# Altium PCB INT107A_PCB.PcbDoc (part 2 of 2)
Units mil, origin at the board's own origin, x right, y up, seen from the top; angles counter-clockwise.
Board outline 2300 x 3400 mil, 4 copper layers (Top Layer, Layer 2 GND, Layer 3 PWR, Bottom Layer), stack 61.634 mil thick; 160 components, 94 nets, 421 pads, 133 vias.
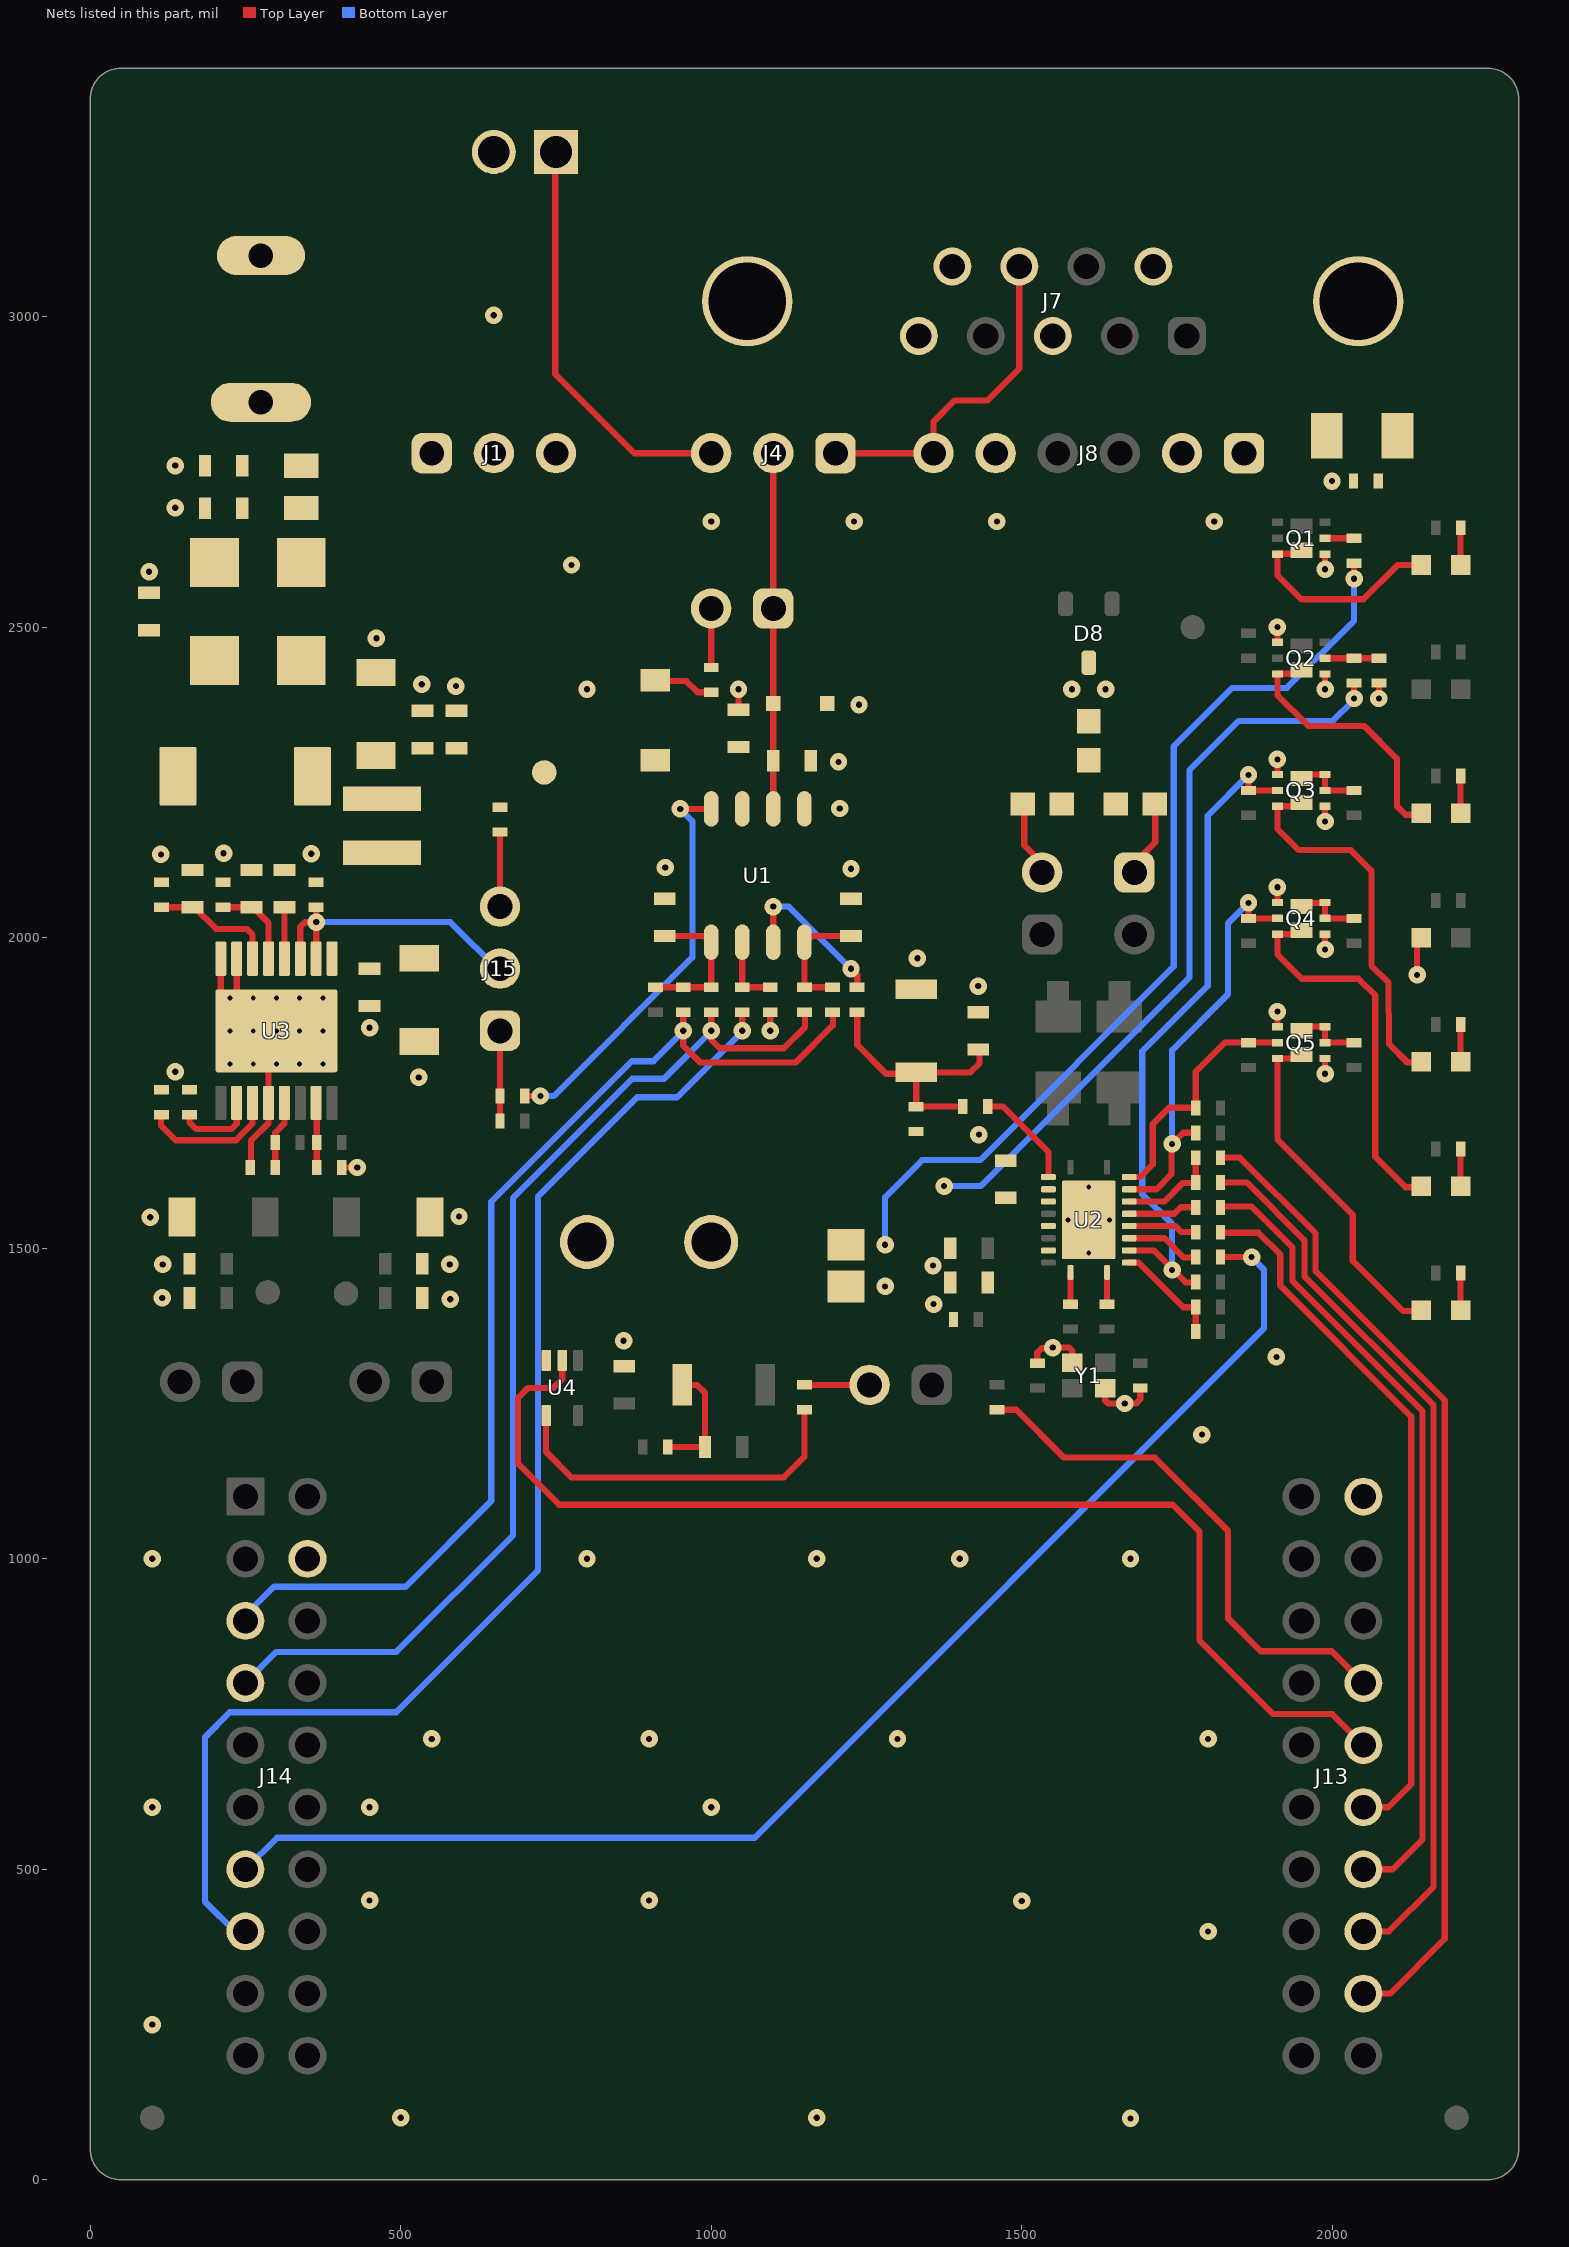
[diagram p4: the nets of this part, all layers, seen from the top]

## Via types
v1: diameter 28, hole 10, Top Layer to Bottom Layer, tented both sides, 114 vias
v2: diameter 19.68, hole 7.87, Top Layer to Bottom Layer, tented both sides, 12 vias
v3: diameter 19.68, hole 7.87, Top Layer to Bottom Layer, tented bottom, 7 vias

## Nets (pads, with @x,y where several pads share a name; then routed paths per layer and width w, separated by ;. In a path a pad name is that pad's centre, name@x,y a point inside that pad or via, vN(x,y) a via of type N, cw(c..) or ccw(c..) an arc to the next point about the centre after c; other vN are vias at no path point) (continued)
DB9_LIN: J4.1 J7.8 J8.6 | length 560.4
  Top Layer w10: J4.1@1188,2780 J4.1@1200,2780 J8.6@1357.87,2780 1357.87,2830.87 1392,2865 1445,2865 1496,2916 1496,3078 J7.8@1499,3081
DB9_VBAT: J1.3 J7.9
EN: R5.2 R52.1 U1.2 | length 117.7
  Top Layer w10: U1.2@1050,1992.72 R52.1@1050,1920 R5.2@1095,1920
FB1: R34.2 R35.2 U3.15 | length 103.4
  Top Layer w10: U3.15@364,1733 365,1732 R34.2@365,1670 R35.2@365,1630
FB2: R29.1 R30.1 U3.13 | length 109.2
  Top Layer w10: R30.1@298,1630 R29.1@298,1670 298,1686 313,1701 U3.13@313,1733
FLTR: C19.1 U2.18
GND: C1.2 C2.2 C3.2 C4.2 C5.2 C6.2 C7.2 C8.2 C9.2 C10.2 C11.1 C12.2 C13.2 C14.2 C15.2 C16.2 C17.2 C19.2 C20.2 C21.2 C22.1 C23.2 C24.2 C25.2 C26.2 C27.1 C28.2 C29.2 C30.2 C31.2 C32.2 D3.2 D7.1 D8.3 D10.1 J2.2 J5.2 J7.3 J7.6 J8.1 J8.2 J8.5 J13.20 J14.22 Q1.4 Q2.1 Q2.4 Q3.1 Q3.4 Q4.1 Q4.4 Q5.1 Q5.4 R5.1 R15.1 R25.1 R30.2 R35.1 R36.2 R37.1 R42.2 R43.1 R45.2 R56.1 S1.1 TP2.1 U1.5 U2.13 U2.21 U3.7 U3.8 U3.12 U3.17@300,1850 U4.3 Y1.2 Y1.4 | length 885.9
  Top Layer w10: U3.17@210,1902 210.43,1902.43 U3.8@210.43,1966.14 ; U3.17@234,1907 236.02,1909.02 U3.7@236.02,1966.14 ; R30.2@259,1631 259,1673 287.2,1701.2 U3.12@287.2,1733.86 287.2,1791.8 U3.17@286,1793 ; R45.2@363.98,2089 R45.2@365,2089 ; R35.1@405,1630 v1(430,1630) ; C20.2@1044,2367 v1(1044,2400) ; v1(1095,1850) R5.1@1095,1879 ; C14.2@1525,1315 1525,1332 1532,1339 v1@1550,1339 ; v1(1550,1340) 1576,1340 1581.3,1334.7 Y1.4@1581.3,1315.67 ; Y1.2@1634.45,1274.33 1634.45,1254.55 1639,1250 v1(1665.66,1250) 1684,1250 1690.75,1256.75 C17.2@1690.75,1275 ; v1@1911,2500 1911.61,2499.39 Q2.1@1911.61,2475.59 ; Q5.1@1911.61,1856.59 v1@1911.61,1879.61 ; Q4.1@1911.61,2056.59 v1@1911.61,2080.39 ; Q3.1@1911.61,2262.59 v1@1911.61,2285.61 ; v1@1988.39,1780.39 Q5.4@1988.39,1805.41 ; v1@1988.39,1980.39 Q4.4@1988.39,2005.41 ; v1@1988.39,2188.39 Q3.4@1988.39,2211.41 ; Q2.4@1988.39,2424.41 1988.39,2400.61 v1@1989,2400 ; v1@1988.39,2593.61 Q1.4@1988.39,2617.41 ; v1(2075,2385) R56.1@2075,2409 ; v1(2136.5,1940) 2136.5,1992.99 D10.1@2143.5,2000
  other v1: 1675,99 500,100 1170,100 100,250 1800,400 1500,449 450,450 900,450 100,600 450,600 1000,600 550,710 900,710 1300,710 1800,710 100,1000 800,1000 1170,1000 1400,1000 1675,1000 1790,1200 1910,1325 859,1351 1358,1410 580,1418 116,1420 1280,1438.54 1357,1472 117,1474 579,1474 97,1550 594,1551 1430.98,1683 529,1775 1988.39,1781 137,1784 450,1855 1911.61,1881 1430,1922 1332,1967 1988.39,1981 1911.61,2081 1225,2111 926,2113 114,2134 356,2135 215,2136 1988.39,2187 1207,2208 1205,2283 1911.61,2287 1238,2375 800,2400 1580.75,2400 1635,2400 1988.39,2400 589,2405 534,2408 461,2482 1911.61,2500 95,2589 1988.39,2593 775,2600 1000,2670 1230,2670 1460,2670 1810,2670 137,2692 1999.5,2735 137,2760 650,3002
  other v2: 225.2,1796.85 262.6,1796.85 300,1796.85 337.4,1796.85 374.8,1796.85 225.2,1850 374.8,1850 225.2,1903.15 262.6,1903.15 300,1903.15 337.4,1903.15 374.8,1903.15
  other v3: 1607.87,1492.5 1574.41,1545.65 1641.34,1545.65 1607.87,1598.8 262.6,1850 300,1850 337.4,1850
GPIO1: Q3.2 R48.1 R62.1 U2.3 | length 1087.8
  Top Layer w10: U2.3@1672.83,1496.43 1712.57,1496.43 1764,1445 R48.1@1781,1445 ; R62.1@1865,2237 v1(1865,2262) ; R62.1@1866,2237 Q3.2@1911.61,2237
  Bottom Layer w10: v1(1742,1465) 1742,1539 1694,1587 1694,1817 1799.4,1922.4 1799.4,2196.4 v1(1865,2262)
GPIO1_LED_INV: Q3.5 Q3.6 Q3.7 R26.1 | length 112.7
  Top Layer w10: Q3.7@1950,2255 1957.59,2262.59 Q3.6@1988.39,2262.59 Q3.5@1988.39,2237 R26.1@2034,2237
GPIO1_LEDA: D9.2 R18.1 | length 62.2
  Top Layer w10: D9.2@2206,1798 2206.5,1798.5 R18.1@2206.5,1860
GPIO1_LEDC: D9.1 Q3.3 Q3.8 | length 617.2
  Top Layer w10: Q3.8@1952,2219 Q3.8@1950.79,2217.79 ; Q3.8@1953.41,2217.79 Q3.8@1950.79,2217.79 ; D9.1@2144,1799 2121,1799 2091.33,1828.67 2090.52,1927.48 2063,1955 2063,2108 2030,2141 1946,2141 1911.61,2175.39 Q3.3@1911.61,2211.41 1944.41,2211.41 Q3.8@1950.79,2217.79
GPIO_RST: J13.17 R46.1 | length 854.8
  Top Layer w10: R46.1@1460,1240 1491,1240 1568,1163 1714,1163 1832,1045 1832,904 1885,851 1999,851 J13.17@2050,800
GPO2: Q5.2 R31.1 R54.1 U2.9 | length 399.8
  Top Layer w10: U2.9@1672.83,1614.54 1690.54,1614.54 1711,1635 1711,1700 1737,1726 R54.1@1779,1726 ; R54.1@1780,1725.65 1780,1784 1827,1831 R31.1@1865,1831 Q5.2@1911.61,1831
GPO2_LED_INV: Q5.5 Q5.6 Q5.7 R32.1 | length 112.2
  Top Layer w10: Q5.7@1950,1850.21 1956.79,1857 Q5.6@1988,1857 ; Q5.5@1988,1831 1988.39,1831.39 Q5.6@1988.39,1856.59 ; Q5.5@1988.39,1831 R32.1@2034,1831
GPO2_LEDA: D12.2 R33.1 | length 62.6
  Top Layer w10: R33.1@2206.5,1460 2206.5,1399.5 D12.2@2208,1398
GPO2_LEDC: D12.1 Q5.3 Q5.8 | length 560.2
  Top Layer w10: Q5.8@1951,1811 1945.41,1805.41 Q5.3@1911.61,1805.41 1911.61,1675.39 2033,1554 2033,1479.56 2113.56,1399 D12.1@2142,1399
ILIM1: R42.1 U3.10 | length 129.6
  Top Layer w10: R42.1@160,1715 160,1703 171.13,1691.87 227.32,1691.87 236,1700.56 U3.10@236,1734
ILIM2: R36.1 U3.11 | length 218.8
  Top Layer w10: R36.1@114,1715 114,1698 138,1674 235,1674 241.13,1680.13 241.13,1680.4 261.61,1700.89 U3.11@261.61,1733.86
INH: J15.1 R59.2 R60.1 | length 140
  Top Layer w10: R60.1@660,1710 660,1750 J15.1@660,1850
JACK_VBAT: J1.1 J2.1
LDO_EN: J15.2 R45.1 U3.2 U3.3 | length 491
  Top Layer w10: U3.3@338.39,1966.14 338.39,2017.39 345.98,2024.98 v1(363.98,2025) ; U3.2@363.98,1966.14 v1(363.98,2025) ; R45.1@363.98,2047.98 v1(363.98,2025)
  Bottom Layer w10: v1(363.98,2025) 580,2025 J15.2@660,1945
LDO_PU: J15.3 R38.2 | length 121.8
  Top Layer w10: R38.2@658,2171 660,2169 J15.3@660,2050
LIN: C10.1 D7.2 J3.1 J4.2 U1.6 | length 579.5
  Top Layer w10: J3.1@1099,2535 1100,2534 D7.2@1100,2377 ; U1.6@1100,2207.28 C10.1@1100,2285 D7.2@1100,2379 ; J3.1@1100,2530 1100,2778 J4.2@1101,2779
LIN_INH: R59.1 U1.8 | length 659.2
  Top Layer w10: R59.1@700,1745 v1(725,1745) ; v1(950,2207.28) U1.8@1000,2207.28
  Bottom Layer w10: v1(725,1745) 746.18,1745 969.67,1968.48 969.67,2187.62 v1(950,2207.28)
LIN_PU: D2.1 R7.2 | length 87.5
  Top Layer w10: D2.1@920,2413 960,2413 978,2395 R7.2@1000,2395
LIN_PU_EN: J3.2 R7.1 | length 92.4
  Top Layer w10: R7.1@999,2438 1000,2439 J3.2@1000,2530
LIN_TERMINAL: J4.3 J5.1 | length 663.6
  Top Layer w10: J5.1@749,3267 749,2907 876,2780 J4.3@1000,2780
LIN_WAKE: R58.1 U1.3 | length 257.8
  Top Layer w10: U1.3@1100,1992.72 v1(1100,2050) ; v1(1225,1950) 1235,1940 R58.1@1235,1920
  Bottom Layer w10: v1(1100,2050) 1125,2050 v1(1225,1950)
LP_UART_RX: J14.3 R39.1 R40.1 | length 1742.7
  Top Layer w10: J14.3@250,900 J14.3@253,900 ; R39.1@955,1880 v1(955,1850) 955,1826 982,1799 1136,1799 1196,1859 R40.1@1196,1882
  Bottom Layer w10: J14.3@250,900 250,909 296,955 508,955 646,1093 646,1574.98 872.02,1801 907,1801 v1@955,1849
LP_UART_TX: J14.4 R41.1 R44.1 | length 1743.9
  Top Layer w10: R41.1@1000,1880 v1(1000,1850) 1000,1836 1014,1822 1117,1822 1151,1856 R44.1@1151,1881
  Bottom Layer w10: J14.4@250,800 300,850 493,850 681,1038 681,1581.09 872.91,1773 924,1773 v1@1001,1850
MCU_RST: J10.2 R47.1 | length 105.4
  Top Layer w10: R47.1@1150,1280 1254,1280 J10.2@1255,1279
nCS: R21.2 R57.2 U2.7 | length 159.9
  Top Layer w10: U2.7@1672.83,1575.17 1729.17,1575.17 1759,1605 R21.2@1780,1605 ; R21.2@1780,1605.65 R57.2@1780,1645.65 R57.2@1780,1646
nINT: Q4.2 R23.1 R55.1 U2.8 | length 684
  Top Layer w10: U2.8@1672.98,1595 1717,1595 1741,1619 v1@1741,1668 ; v1(1742,1668) 1760,1686 R55.1@1780,1686 ; R23.1@1865,2030 R23.1@1865,2031 ; v1(1865,2056) R23.1@1865,2031 ; Q4.2@1911.61,2031 R23.1@1865,2031
  Bottom Layer w10: v1(1742,1668) 1742,1819 1832,1909 1832,2023 v1(1865,2056)
NINT_LED_INV: Q4.5 Q4.6 Q4.7 R24.1 | length 113.8
  Top Layer w10: Q4.7@1950,2050.21 1955.79,2056 Q4.6@1988.39,2056 ; Q4.5@1988,2031 1988.39,2031.39 Q4.6@1988.39,2056 ; Q4.5@1988.39,2031 R24.1@2035,2031 ; Q4.6@1988.39,2056.59 Q4.6@1988.39,2056 ; Q4.6@1989,2056 Q4.6@1988.39,2056
NINT_LEDA: D11.2 R28.1 | length 62.2
  Top Layer w10: R28.1@2206.5,1660 2206.5,1598.5 D11.2@2207,1598
NINT_LEDC: D11.1 Q4.3 Q4.8 | length 614.3
  Top Layer w10: Q4.8@1951,2012 1944.41,2005.41 Q4.3@1911.61,2005.41 1911.61,1973.39 1951,1934 2042,1934 2069,1907 2069,1647 2118,1598 D11.1@2144,1598
nWRKQ: R53.1 R61.1 U2.2 | length 178.6
  Top Layer w10: U2.2@1672.83,1476.75 1688.25,1476.75 1760,1405 R53.1@1780.65,1405 ; R61.1@1780,1365.65 1780,1404 1781,1405 R53.1@1780.65,1405 ; R53.1@1780,1405.65 R53.1@1780.65,1405
OSC1: R20.1 U2.1 | length 52.2
  Top Layer w10: R20.1@1637,1409 1637.4,1409.4 U2.1@1637.4,1461
OSC2: R17.1 U2.20 | length 51.3
  Top Layer w10: U2.20@1578.35,1461 1578.35,1410.65 R17.1@1579,1410
RST: J13.16 U4.2 | length 1869.9
  Top Layer w10: 760,1289 746,1275 705,1275 689,1259 689,1153 755,1087 1743,1087 1786,1044 1786,869 1905,750 2000,750 J13.16@2050,700 ; 760,1290 U4.2@760,1319.29
RST_INV: R47.2 U4.4 | length 580.1
  Top Layer w10: U4.4@735,1229 734,1228 734,1172 775,1131 1117,1131 1150,1164 R47.2@1150,1240
RST_SW: C18.2 R22.1 S2.1 | length 190.3
  Top Layer w10: R22.1@930,1180 C18.2@990,1180 990,1267 977,1280 S2.1@953.07,1280 ; C18.2@990,1185 C18.2@991,1185
SCLK: R50.1 U2.4 | length 119.1
  Top Layer w10: U2.4@1672.83,1516.12 1729.88,1516.12 1761,1485 R50.1@1779,1485
SDI: R49.2 U2.5 | length 110.2
  Top Layer w10: U2.5@1672.83,1535.8 1747.2,1535.8 1757,1526 R49.2@1779,1526
SDO: R51.2 U2.6 | length 112.5
  Top Layer w10: U2.6@1672.83,1555.49 1745.49,1555.49 1756,1566 R51.2@1781,1566
SENSE1: C30.1 R37.2 U3.5 | length 141.1
  Top Layer w10: R37.2@215,2048 216,2049 C30.1@260,2049 C30.1@261,2049 ; C30.1@261,2050 287.2,2023.8 U3.5@287.2,1966.14
SENSE2: C32.1 R43.2 U3.6 | length 203.8
  Top Layer w10: R43.2@115,2049 C32.1@165,2049 166,2048 C32.1@168,2048 ; C32.1@168,2049 203,2014 252,2014 261.61,2004.39 U3.6@261.61,1966.14
SHIELD_GND: C15.1 J7.5 J7.10 J7.11 R15.2
SPI_CLK: J14.7 R50.2 | length 2173.9
  Top Layer w10: R50.2@1820,1485.65 1869.65,1485.65 v1@1870,1486
  Bottom Layer w10: J14.7@250,500 301,551 1070,551 1890,1371 1890,1465.65 v1(1870,1485.65)
SPI_CS_0: J13.13 R21.1 | length 1442.5
  Top Layer w10: R21.1@1821,1606 1862,1606 1955,1513 1955,1455 2163,1247 2163,472 2091,400 J13.13@2050,400
SPI_CS_1: J13.12 R57.1 | length 1593.6
  Top Layer w10: R57.1@1820,1645 1821,1646 1851,1646 1973,1524 1973,1463 2181,1255 2181,388 2093,300 J13.12@2050,300
SPI_MISO: J13.14 R51.1 | length 1296.8
  Top Layer w10: R51.1@1821,1567 1870,1567 1936,1501 1936,1447 2145,1238 2145,548 2097,500 J13.14@2050,500
SPI_MOSI: J13.15 R49.1 | length 1142.2
  Top Layer w10: R49.1@1821,1525 1881,1525 1916,1490 1916,1440 2127,1229 2127,637 2090,600 J13.15@2050,600
Split_Term: C11.2 R11.1 R12.2
TermH: J6.2 R11.2 | length 126.1
  Top Layer w10: R11.2@1504,2213 1504,2148.79 J6.2@1547.79,2105
TermL: J9.1 R12.1 | length 129.2
  Top Layer w10: J9.1@1666.21,2105 1715,2153.79 R12.1@1715,2214
TLIN_EN: J14.8 R52.2 | length 2071.1
  Top Layer w10: v1(1050,1850) R52.2@1050,1880
  Bottom Layer w10: J14.8@250,400 233,400 185,448 185,713 225,753 493,753 721,981 721,1583 881,1743 945,1743 1051,1849 v1@1051,1851
TLIN_RXD: C8.1 R6.1 R39.2 R41.2 U1.1 | length 239.3
  Top Layer w10: R6.1@910,1920 R39.2@955,1920 ; C8.1@925,2002.72 988.28,2002.72 U1.1@1001,1990 ; R39.2@956,1920 R41.2@1000,1920 1000,1983 U1.1@1004,1987 ; U1.1@998.72,1992.72 U1.1@999,1993
TLIN_TXD: C9.1 R40.2 R44.2 U1.4 | length 195.6
  Top Layer w10: R44.2@1150,1920 R40.2@1195,1920 ; R44.2@1150,1921 U1.4@1150,1992.72 ; U1.4@1151,1991 1162.72,2002.72 C9.1@1225,2002.72
VBAT: C4.1 D1.1 D3.1 L1.2
VBAT_EXT: C6.1 J1.2 R1.2
VBAT_EXT_R: C5.1 D1.2 R1.1
VCC: C31.1 U3.4 | length 84.2
  Top Layer w10: C31.1@312,2049 C31.1@312.8,2048.2 ; U3.4@312.8,1966.14 C31.1@312.8,2049.2
VCCOUT: C21.1 R27.2 TP1.1 U2.16 | length 1516.1
  Top Layer w10: v1@2035,2579 R27.2@2035,2603
  Bottom Layer w10: v1@1280.46,1505 v1(1280,1505.47) 1280,1582.34 1339.66,1642 1433,1642 1744.74,1953.74 1744.74,2307.87 1838.87,2402 1926.75,2402 2035,2510.25 v1(2035,2578)
VCCOUT_LED: Q1.5 R27.1 | length 46.6
  Top Layer w10: Q1.5@1988.39,2643 R27.1@2035,2643
VCCOUT_LEDA: D4.2 R2.1 | length 59.5
  Top Layer w10: D4.2@2206.5,2600 R2.1@2206.5,2659.5
VCCOUT_LEDC: D4.1 Q1.3 Q1.8 | length 338.6
  Top Layer w10: Q1.3@1911,2618 Q1.8@1945,2618 ; Q1.3@1911.61,2617.41 1911.61,2583.39 1950,2545 2050,2545 2105,2600 D4.1@2143.5,2600
VIN: C25.1 C26.1 L3.2 U3.1
VSUP: C1.1 C2.1 C3.1 C12.1 C20.1 D2.2 L1.1 L3.1 R9.1 R13.2 R38.1 TP5.1 U1.7 U2.14 | length 1206.9
  Top Layer w10: R9.1@2034,2410 2035,2409 v1(2035,2385)
  Bottom Layer w10: v1(1375,1600) 1434.18,1600 1769.82,1935.63 1769.82,2269.82 1849,2349 2001,2349 v1@2036,2384
VSUP_LED: Q2.5 R9.2 R56.2 | length 87.6
  Top Layer w10: Q2.5@1988.39,2450 R9.2@2035,2450 R56.2@2075,2450 R56.2@2076,2450
VSUP_LEDA: D6.2 R4.1 | length 62.2
  Top Layer w10: R4.1@2206.5,2260 2206.5,2198.5 D6.2@2207,2198
VSUP_LEDC: D6.1 Q2.3 Q2.8 | length 432.8
  Top Layer w10: Q2.3@1911,2425 1945,2425 1950,2430 Q2.8@1950,2430.79 1949.21,2430 Q2.8@1949.21,2429.79 ; Q2.3@1911.61,2424.41 1911.61,2390.39 1961,2341 2051,2341 2104,2288 2104,2212 2118,2198 D6.1@2143,2198
WAKE: R16.2 U2.12 | length 168.7
  Top Layer w10: R16.2@1445,1728 1470,1728 1542.91,1655.09 U2.12@1542.91,1614.54
WAKE_SW: C16.1 R13.1 R16.1 R58.2 S1.2 | length 416.1
  Top Layer w10: R58.2@1235,1880 1235,1827.42 1281.42,1781 S1.2@1330,1781 ; 1395,1728 R13.1@1330,1728 S1.2@1330,1781 ; C16.1@1432,1819 1432,1798 1417.07,1783.07 S1.2@1330,1783.07 S1.2@1330,1781
pads on no net: FID1.1 FID2.1 FID3.1 J7.1 J7.4 J13.11 J13.18 J13.19 J13.34 J13.35 J13.36 J13.37 J13.38 J13.39 J13.40 J14.2 J14.6 J14.9 J14.10 J14.23 J14.24 J14.25 J14.26 J14.27 J14.28 J14.29 J14.30 Q1.1 Q1.2 Q1.6 Q1.7 SH-J1.0 SH-J2.0 SH-J3.0 SH-J4.0 SH-J5.0 SH-J6.0 SH-J7.0 SH-J8.0 SH-J9.0 U3.9 U3.17@300,1850 U4.1

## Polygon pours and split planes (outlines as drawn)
GND on Top Layer "TOP_LAYER_GND_P153" (solid, remove dead copper, pour order 153): 2085,1055 1865,1055 1725.33,1196.33 1908,1379 2085,1202
GND on Top Layer "TOP_LAYER_GND_P152" (solid, remove dead copper, pour order 152): 25,1035 1735,1035 1735,852 1870,717 1870,290 1820,240 1820,25 25,25
GND on Top Layer "TOP_LAYER_GND_P151" (solid, remove dead copper, pour order 151): 1716,2573 1898,2573 1898,2709 2040,2709 2040,2849 1716,2849
GND on Top Layer "TOP_LAYER_GND_P147" (solid, remove dead copper, pour order 147): 893,2047 1267,2047 1267,1867 1268,1868 1466,1868 1466,1970 1393,2043 1393,2401 1393,2445 1500,2552 1500,2832 1416,2832 1416,2719 1167,2719 1167,2460 1138,2460 1138,2150 893,2150
GND on Top Layer "TOP_LAYER_GND_P143" (solid, remove dead copper, pour order 143): 427,2353 691,2353 860,2353 860,2481 942,2481 942,2588 1046,2588 1046,2721 722,2721 722,2588 427,2588
GND on Top Layer "TOP_LAYER_GND_P131" (solid, remove dead copper, pour order 131): 25,1364 174,1364 174,1619 266,1619 266,1643 114,1643 75,1682 75,1748 176,1748 176,1787 408,1787 517,1678 517,1364 836,1364 836,1297 884,1297 884,1364 1397,1364 1397,1454 1159,1454 1118,1413 896,1413 896,1506 589,1813 589,1912 176,1912 176,1993 78,1993 78,2082 377,2082 377,2168 25,2168
Split_Term on Top Layer "TOP_LAYER_SPLIT_TERM_P127" (solid, remove dead copper, pour order 127): 1554,2196 1554,2291 1570,2307 1646,2307 1662,2291 1662,2196
GND on Top Layer "TOP_LAYER_GND_P125" (solid, remove dead copper, pour order 125): 1539,2438 1589,2488 1627,2488 1677,2438 1677,2331 1539,2331
VSUP on Top Layer "TOP_LAYER_VSUP_P121" (solid, remove dead copper, pour order 121): 731.71,1804.87 887.71,1648.87 1166.71,1648.87 1235.71,1579.87 1444,1579.87 1444,1602 1350,1696 1292,1696 1220,1768 902.58,1768 858.71,1811.87 858.71,2177 910,2177 910,2262 1062,2262 1062,2328.87 858.71,2328.87 274.71,2328.87 274.71,2202.87 731.71,2202.87
3V3 on Top Layer "TOP_LAYER_3V3_P101" (solid, remove dead copper, pour order 101): 777,1261 897,1261 897,1168 789,1168 777,1180
SHIELD_GND on Top Layer "TOP_LAYER_SHIELD_GND_P097" (solid, remove dead copper, pour order 97): 1861,3152 1862,3153 1862,2900 2068,2900 2068,2710 2277,2710 2277,3373 820,3373 820,2898 942,2898 1386,2898 1386,3025 1289,3025 1289,3152
5V_LP on Top Layer "TOP_LAYER_5V_LP_P077" (solid, remove dead copper, pour order 77): 520,1325 520,1176 317,1176 317,1056 659,1056 659,1325
3V3_LP on Top Layer "TOP_LAYER_3V3_LP_P071" (solid, remove dead copper, pour order 71): 174,1335 174,1176 280,1176 280,1056 25,1056 25,1335
5V0 on Top Layer "TOP_LAYER_5V0_P069" (solid, remove dead copper, pour order 69): 372,1593 372,1207 482,1207 482,1593
3V3 on Top Layer "TOP_LAYER_3V3_P067" (solid, remove dead copper, pour order 67): 346,1593 203,1593 203,1206 346,1206
VIN on Top Layer "TOP_LAYER_VIN_P061" (solid, remove dead copper, pour order 61): 403,1940 403,2168 589,2168 589,1940
GND on Top Layer "TOP_LAYER_GND_P059" (solid, remove dead copper, pour order 59): 246,2535 246,2644 197,2644 197,2947 692,2947 692,3374 25,3374 25,2535
VBAT on Top Layer "TOP_LAYER_VBAT_P055" (solid, remove dead copper, pour order 55): 25,2202 245,2202 245,2354 380,2354 380,2513 25,2513
VBAT_EXT_R on Top Layer "TOP_LAYER_VBAT_EXT_R_P049" (solid, remove dead copper, pour order 49): 229,2711 380,2711 380,2539 278,2539 278,2671 229,2671
no net on Top Layer "TOP_LAYER_NONET_P047" (solid, remove dead copper, pour order 47): 606,2832
VBAT_EXT on Top Layer "TOP_LAYER_VBAT_EXT_P045" (solid, remove dead copper, pour order 45): 608,2920 692,2920 692,2617 403,2617 403,2741 223,2741 223,2780 460,2780 460,2704 608,2704
JACK_VBAT on Top Layer "TOP_LAYER_JACK_VBAT_P043" (solid, remove dead copper, pour order 43): 150,2810 492,2810 492,2730 582,2730 582,2921 150,2921
GND on Bottom Layer "BOTTOM_LAYER_GND_P155" (solid, remove dead copper, pour order 155): 12.76,42.56 11.76,43.56 11.76,3392.56 2261.76,3392.56 2262.76,3391.56 2262.76,43.56
no net on Bottom Layer "BOTTOM_LAYER_NONET_P123" (solid, remove dead copper, pour order 123): 1537,2319
DB9_VBAT on Bottom Layer "BOTTOM_LAYER_DB9_VBAT_P113" (solid, remove dead copper, pour order 113): 705,2674 705,3207 1440,3207 1440,3025 1217,3025 1118,3124 938,3124 938,2674
no net on Drill Drawing "NONET_L-01_P-001" (solid, remove dead copper): 2082,1134
GND on Layer 2 GND (split plane): 2254.69,3379.62 2259.27,3378.52 2263.62,3376.72 2267.63,3374.26 2271.21,3371.21 2274.26,3367.63 2276.72,3363.62 2278.52,3359.27 2279.62,3354.69 2279.95,3350.5 2279.9,3350 2279.9,50 2279.95,49.5 2279.62,45.31 2278.52,40.73 2276.72,36.38 2274.26,32.37 2271.21,28.79 2267.63,25.74 2263.62,23.28 2259.27,21.48 2254.69,20.38 2250.5,20.05 2250,20.1 50,20.1 49.5,20.05 45.31,20.38 40.73,21.48 36.38,23.28 32.37,25.74 28.79,28.79 25.74,32.37 23.28,36.38 21.48,40.73 20.38,45.31 20.05,49.5 20.1,50 20.1,3350 20.05,3350.5 20.38,3354.69 21.48,3359.27 23.28,3363.62 25.74,3367.63 28.79,3371.21 32.37,3374.26 36.38,3376.72 40.73,3378.52 45.31,3379.62 49.5,3379.95 50,3379.9 2250,3379.9 2250.5,3379.95
5V0 on Layer 3 PWR (split plane): 2254.69,3379.62 2259.27,3378.52 2263.62,3376.72 2267.63,3374.26 2271.21,3371.21 2274.26,3367.63 2276.72,3363.62 2278.52,3359.27 2279.62,3354.69 2279.95,3350.5 2279.9,3350 2279.9,50 2279.95,49.5 2279.62,45.31 2278.52,40.73 2276.72,36.38 2274.26,32.37 2271.21,28.79 2267.63,25.74 2263.62,23.28 2259.27,21.48 2254.69,20.38 2250.5,20.05 2250,20.1 50,20.1 49.5,20.05 45.31,20.38 40.73,21.48 36.38,23.28 32.37,25.74 28.79,28.79 25.74,32.37 23.28,36.38 21.48,40.73 20.38,45.31 20.05,49.5 20.1,50 20.1,3350 20.05,3350.5 20.38,3354.69 21.48,3359.27 23.28,3363.62 25.74,3367.63 28.79,3371.21 32.37,3374.26 36.38,3376.72 40.73,3378.52 45.31,3379.62 49.5,3379.95 50,3379.9 2250,3379.9 2250.5,3379.95
3V3 on Layer 3 PWR (split plane): 2064.9,2225.1 1950,2225.1 1948.05,2224.71 1946.4,2223.6 1945.29,2221.95 1944.9,2220 1944.9,880.1 130.1,880.1 130.1,1644.9 344.9,1644.9 344.9,1130 345.29,1128.05 346.4,1126.4 348.05,1125.29 350,1124.9 750,1124.9 751.95,1125.29 753.6,1126.4 754.71,1128.05 755.1,1130 755.1,1757.89 891.11,1893.9 1790,1893.9 1791.95,1894.29 1793.6,1895.4 1794.71,1897.05 1795.1,1899 1795.1,2554.9 2064.9,2554.9

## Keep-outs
Keep-Out Layer:
  text ".Layer_Name" at 577,-858.49 h60

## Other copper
Top Layer:
  region net GND: 1569,1590 1516,1590 1505,1601 1505,1651 1431,1651 1381,1701 1474,1701 1520,1655 1520,1643 1520,1607 1527,1600 1569,1600
  region net GND: 1398,1701 1398,1684 1381,1701
  region net 5V0: 491,1591 491,1590 481,1580 481,1591
  region net 5V0: 403,1578 403,1595 423,1595 423,1578
  region: 402,1578
  region net GND: 176,1802 419,1802 419,1787 176,1787
  region net GND: 176,1912 419,1912 419,1896 176,1896
  region net GND: 1396,1521 1360,1521 1292,1453 1396,1453 1396,1463 1374,1463 1374,1478 1396,1478
  region net VSUP: 418,2263
  region net GND: 896,1505 896,1582 819,1582
  region net 5V0: 372,1593 372,1590 491,1590 491,1668 398,1761 383,1761 383,1657 398,1657 439,1657 456,1640 456,1605 384,1605
  region net VIN: 381,1993 409,1993 409,1940 382,1940 381,1941
  region net GND: 727,1305 727,1370 742,1370 742,1305
  region net FLTR: 1528,1492 1551,1492 1551,1501 1516,1501 1478,1463 1434,1463 1434,1427 1500,1427 1518,1445 1518,1482
  region net 3V3: 1552,1521 1434,1521 1434,1478 1463,1478 1477,1478 1510,1511 1551,1511 1552,1512
  region net VCCOUT: 1554,1541 1170,1541 1129,1582 932,1582 932,1439 1101,1439 1142,1480 1295,1480 1346,1531 1554,1531
  region net VSUP: 1062,2179 1038,2179 1038,2265 1062,2265
  region net GND: 1529,1598
  region net GND: 1529,1599
  region net VSUP: 1552,1570 1245,1570 1225,1590 1491,1590 1501,1580 1552,1580
  region net 3V3: 346,1591 346,1761 331,1761 331,1692 324,1685 324,1591
  text ".Layer_Name" at 577,-858.49 h60
Bottom Layer:
  text ".Layer_Name" at 577,-858.49 h60
Layer 2 GND (plane layer: these items are gaps in the copper):
  text ".Layer_Name" at 577,-861 h60
Layer 3 PWR (plane layer: these items are gaps in the copper):
  lines w10: 125,875 1950,875 1950,2220 2070,2220 2070,2560 1790,2560 1790,1899 1281,1899 889,1899 750,1760 750,1130 350,1130 350,1650 125,1650 125,875
  text ".Layer_Name" at 577,-856 h60

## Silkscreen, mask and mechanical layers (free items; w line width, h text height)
Top Overlay:
  region: 2298.5,1100.5 2298.5,1146 2157.75,1146 2112,1100.25 2156.5,1055.25 2298.5,1055.25 2298.5,1100.5 2290.5,1100.5 2290.5,1063.25 2291,1062.75 2159.5,1062.75 2122.5,1100 2122.5,1101 2159.5,1138 2290.5,1138 2290.5,1100.5
  region: 599.75,1000.5 599.75,1046 459,1046 413.25,1000.25 457.75,955.25 599.75,955.25 599.75,1000.5 591.75,1000.5 591.75,963.25 592.25,962.75 460.75,962.75 423.75,1000 423.75,1001 460.75,1038 591.75,1038 591.75,1000.5
  region: 599.5,1101 599.5,1145.5 458,1145.5 413,1100.5 457.5,1055.5 599.5,1055.5 599.5,1101 560.5,1101 560.5,1075 480,1075 480,1127 560.5,1127 560.5,1101
  region: 0.5,1100 0.5,1055.5 142,1055.5 187,1100.5 142.5,1145.5 0.5,1145.5 0.5,1100 22,1100 22,1126 138,1126 138,1074 22,1074 22,1100
  text "GND" at 665,3014 h30 r90
  text "LIN_TERM" at 772,2874 h30 r90
  text "LIN" at 1099,2631 h30 r90
  text "DB9" at 1208,2622 h30 r90
  text "GND" at 1876,2622 h30 r90
  text "GND" at 1474,2616 h30 r90
  text "GND" at 1777,2616 h30 r90
  text "TERM" at 1002,2602 h30 r90
  text "VBAT" at 666,2589 h30 r90
  text "CANL" at 1677,2589 h30 r90
  text "DB9" at 768,2588 h30 r90
  text "JACK" at 565,2587 h30 r90
  text "CANH" at 1571,2586 h30 r90
  text "VCCOUT" at 2265,2525 h30 r90
  text "LIN_DB9" at 1374,2512 h30 r90
  text "LIN PULLUP" at 649,2510 h30
  text "3.3V" at 2265,2350 h30 r90
  text "VSUP" at 676,2307 h30
  text "VSUP" at 2265,2145 h30 r90
  text "LDO_PU" at 724,2033 h30
  text "5V" at 2265,1975 h30 r90
  text "WAKE" at 1277,1945 h30
  text "LDO_EN" at 724,1941 h30
  text "INH" at 725,1835 h30
  text "GPIO1" at 2265,1735 h30 r90
  text "VCCOUT" at 917,1607 h30
  text "GND" at 761.39,1606 h30
  text "nINT" at 2265,1550 h30 r90
  text "3V3" at 245,1358 h30
  text "5V" at 390,1357 h30
  text "RESET" at 957,1351 h30
  text "GPO2" at 2265,1345 h30 r90
  text "CAN_RST" at 1371,1030 h30 r90
  text "MCU_RST" at 1274,1024 h30 r90
  text "UARX" at 76,880 h30
  text "GPIO" at 2109,814 h30
  text "UATX" at 73.9,780 h30
  text "RESET" at 2110,773 h30
  text "GPIO1" at 66,685.51 h30
  text "RST" at 2110,677 h30
  text "MOSI" at 2110,577 h30
  text "SCLK" at 73.9,484 h30
  text "MISO" at 2110,477 h30
  text "LIN_EN" at 24,382 h30
  text "nCS_0" at 2110,377 h30
  text "nWKRQ" at 1729.3,375 h30
  text "nCS_1*" at 2110,277 h30
  text "GPO2" at 1762,273 h30
  text "nINT" at 1758,172 h30
  text "BOOSTXL-CANFD-LIN" at 588,155 h40
  text "Rev 1.0" at 1300,155 h40
  text ".Layer_Name" at 577,-858.49 h30
Bottom Overlay:
  drawing of 3493 lines, arcs and shapes, not listed
  text "40" at 1998,1167 h55
  text "20" at 2103,1167 h55
  text "1" at 297,1160 h55
  text "21" at 397.5,1160 h55
  text "J4" at 1902.5,1158 h72.83
  text "J1" at 202.5,1154 h72.83
  text "J3" at 479,1154 h72.83
  text "J2" at 2185,1153 h72.83
  text "UARX" at 271.5,841 h30
  text "GPIO" at 2335,780 h30
  text "UATX" at 271.5,751 h30
  text "RESET" at 2318,740 h30
  text "GPIO1" at 202.5,645 h30
  text "RST" at 2253,640 h30
  text "MOSI" at 2289,544 h30
  text "SCLK" at 202.5,445 h30
  text "MISO" at 2296,437 h30
  text "SPI to CANFD SBC + LIN BoosterPack" at 1693,393 h72.83
  text "LIN_EN" at 195,349 h30
  text "nCS_0" at 2316,341 h30
  text "nWKRQ" at 1940,337 h30
  text "BOOSTXL-CANFD-LIN" at 1693,335.9 h72.83
  text "Rev 1.0" at 1693,268.04 h60
  text "GPO2" at 1955,241 h30
  text "nCS_1*" at 2325,236 h30
  text "nINT" at 1935,136 h30
  text "31" at 1998,90 h55
  text "10" at 300,89 h55
  text "30" at 400,89 h55
  text "11" at 2101,89 h55
  text "INT107A" at 1692,35 h72.83
  text ".Layer_Name" at 577,-858.49 h60
Top Paste:
  text ".Layer_Name" at 577,-858.49 h60
Bottom Paste:
  text ".Layer_Name" at 577,-858.49 h60
Top Solder:
  text ".Layer_Name" at 577,-858.49 h60
  text ".Layer_Name" at 577,-858.49 h60
Bottom Solder:
  text ".Layer_Name" at 577,-858.49 h60
Drill Guide:
  text ".Layer_Name" at 577,-858.49 h60
M1 Board Outline:
  the board outline again, w10
  text ".Layer_Name" at 577,-858.49 h60
M2 Board Dimensions:
  rectangle: 0,-275 125,-150
  rectangle: 125,-400 500,-275
  lines w7: 0,-275 1000,-275 ; 125,-400 125,-150 ; 250,-400 250,-150 ; 500,-400 500,-150 ; 750,-400 750,-150 ; 0,-400 1000,-400 1000,-150 0,-150 0,-400
  text ".Layer_Name" at 577,-858.49 h60
M3 3D STEP Top:
  text ".Layer_Name" at 577,-858.49 h60
M4 3D STEP Bottom:
  text ".Layer_Name" at 577,-858.49 h60
M5 Assembly Top:
  lines w10: -292,-930.17 6308,-930.17 ; -292,-726.83 6310,-726.83 ; -292,-523.5 -292,-1133.5 3713,-1133.5 6310,-1133.5 6310,-523.5 -291.5,-523.5 -291.5,-1133.5 1284,-1133.5 ; 2173,-1133.5 2173,-523.5 ; 3440,-726.83 3440,-523.5 ; 4280,-726.83 4280,-523.5 ; 4902,-1140 4902,-937.17
  text "COMPONENTS MARKED 'DNP' SHOULD NOT BE POPULATED." at 1153.5,-318.5 h60
  text "ASSEMBLY VARIANT:" at 1153,-434 h60
  text ".VariantName" at 2189,-434 h60
  text "PCB VIEWED FROM TOP SIDE" at -228.5,-655.67 h60
  text "BOARD #:" at 2248,-655.67 h60
  text ".PRJ_Number" at 2793.5,-655.67 h60
  text "REV:" at 3638,-655.67 h60
  text ".PCB_Rev" at 3929.5,-655.67 h60
  text "SVN REV:" at 4476,-655.67 h60
  text ".VersionControl_RevNumber" at 4982,-655.67 h60
  text "TID #:" at 2248,-859 h60
  text ".TID" at 2793.5,-859 h60
  text "PLOT NAME =" at -228.5,-1064.34 h60
  text ".plot_File_Name" at 577,-1064.34 h60
  text "GENERATED    :" at 2250,-1064.34 h60
  text ".Print_Date" at 3119.5,-1064.34 h60
  text ".Print_Time" at 3848.5,-1064.34 h60
  text "TEXAS INSTRUMENTS" at 5113,-1064.34 h60
M6 Assembly Bottom:
  lines w10: -292.5,-727.33 6309.5,-727.33 ; -290.5,-930.67 6309.5,-930.67 ; 1115.5,-1140.5 1115.5,-937.67 ; 1737.5,-727.33 1737.5,-524 ; 2577.5,-727.33 2577.5,-524 ; 3844.5,-1134 3844.5,-524 ; 4733.5,-1134 6309,-1134 6309,-524 -292.5,-524 -292.5,-1134 2304.5,-1134 6309.5,-1134 6309.5,-524
  text "COMPONENTS MARKED 'DNP' SHOULD NOT BE POPULATED." at 6102,-318 h60
  text ".VariantName" at 5058,-434 h60
  text "ASSEMBLY VARIANT:" at 6097,-434 h60
  text ".VersionControl_RevNumber" at 1035.5,-656.17 h60
  text "SVN REV:" at 1541.5,-656.17 h60
  text ".PCB_Rev" at 2088,-656.17 h60
  text "REV:" at 2379.5,-656.17 h60
  text ".PRJ_Number" at 3224,-656.17 h60
  text "BOARD #:" at 3769.5,-656.17 h60
  text "PCB VIEWED FROM BOTTOM SIDE" at 6246,-656.17 h60
  text ".TID" at 3224,-859.5 h60
  text "TID #:" at 3769.5,-859.5 h60
  text "TEXAS INSTRUMENTS" at 904.5,-1064.84 h60
  text ".Print_Time" at 2169,-1064.84 h60
  text ".Print_Date" at 2898,-1064.84 h60
  text "GENERATED    :" at 3767.5,-1064.84 h60
  text ".plot_File_Name" at 5440.5,-1064.84 h60
  text "PLOT NAME =" at 6246,-1064.84 h60
M9 Title Sheet:
  drawing of 57 lines, arcs and shapes, not listed
  text "1" at 739.84,8036.5 h70
  text "2" at 3235.5,8036.5 h70
  text "3" at 5724.84,8036.5 h70
  text "4" at 8231.51,8036.5 h70
  text "5" at 10730.5,8036.5 h70
  text "6" at 13235.5,8036.5 h70
  text "A" at -416.5,6893.5 h70
  text "A" at 14383.5,6893.5 h70
  text "B" at -416.5,4513.5 h70
  text "B" at 14383.5,4513.5 h70
  text "C" at -416.5,2138.5 h70
  text "C" at 14383.5,2138.5 h70
  text "PROJECT TITLE:" at 11343.5,277.5 h45
  text ".PRJ_Title" at 11393.5,144.17 h70
  text "DESIGNED FOR:" at 11343.5,-23.5 h45
  text ".PRJ_Customer" at 11393.5,-163.5 h70
  text "D" at -416.5,-231.5 h70
  text "D" at 14383.5,-231.5 h70
  text "FILE NAME:" at 11343.5,-323.5 h45
  text ".PCB_File_Name_No_Path" at 11393.5,-443.5 h70
  text "Texas Instruments (TI) and/or its licensors do not warrant the accuracy or completeness of this specification" at 6374,-605.34 h45
  text "ENGINEER:" at 11343.5,-613.5 h45
  text "LAYOUT BY:" at 12848.5,-613.5 h45
  text "or any information contained therein. TI and/or its licensors do not warrant that this design will meet" at 6329.01,-718 h45
  text ".PRJ_Engineer" at 11393.5,-768.49 h70
  text ".PCB_Layout" at 12899,-768.49 h70
  text "the specifications, will be suitable for your application or fit for any particular purpose, or will operate in" at 6329.01,-830.67 h45
  text ".Layer_Name" at 577,-858.49 h60
  text "ALTIUM DESIGNER VERSION:" at 12848.5,-923.5 h45
  text "an implementation. TI and/or its licensors do not warrant that the design is production worthy. You should" at 6329.01,-943.33 h45
  text "completely validate and test your design implementation to confirm the system functionality for your application." at 6374,-1056 h45
  text ".print_Scale" at 11393.5,-1056.83 h70
  text ".Application_BuildNumber" at 12899,-1056.83 h70
  text "1" at 739.84,-1263.5 h70
  text "2" at 3235.5,-1263.5 h70
  text "3" at 5724.84,-1263.5 h70
  text "4" at 8231.51,-1263.5 h70
  text "5" at 10730.5,-1263.5 h70
  text "6" at 13235.5,-1263.5 h70
M10 Fab Notes:
  drawing of 173 lines, arcs and shapes, not listed
  text "DESIGN INFORMATION" at 12378.02,6201 h60
  text "MIN. TRACK WIDTH:" at 11733.46,6021 h60
  text "10" at 12829.7,6021 h60
  text "MIL" at 12984.46,6021 h60
  text "MIN. CLEARANCE:" at 11733.46,5889 h60
  text "0.2" at 12769.7,5889 h60
  text "mm" at 12984.46,5889 h60
  text "19.6" at 12737,5760 h60
  text "MIN. VIA PAD SIZE:" at 11733.46,5757 h60
  text "MIL" at 12984.46,5757 h60
  text "0.05mm (2MIL)" at 12428.46,5615.29 h60
  text "MINIMUM ANNULAR RING" at 11404.23,5611 h60
  text "EXTERNAL" at 13136.46,5611 h60
  text "PER" at 11604.23,5493 h60
  text "IPC-D-275 CLASS 2 LEVEL C" at 11824.23,5493 h60
  text "MIL, HOLES" at 13312.46,5380.71 h60
  text "+/-" at 12920,5380 h60
  text "+/-" at 13774,5380 h60
  text "REGISTRATION TOLERANCES:" at 11404.23,5375 h60
  text "METAL" at 12604,5375 h60
  text "5" at 13180.2,5375 h60
  text "3" at 14013.2,5375 h60
  text "MIL" at 14129.46,5375 h60
  text "+/-" at 13774,5262 h60
  text "HOLE SIZE TOLERANCE (UNLESS OTHERWISE SPECIFIED):" at 11404.23,5257 h60
  text "3" at 14013.2,5257 h60
  text "MIL" at 14129.46,5257 h60
  text "MATERIAL:" at 11329.46,5047.54 h60
  text "FR-4 High Tg" at 12315.9,4907.21 h60
  text "FR-408" at 11750.46,4898.64 h60
  text "OTHER" at 13238.46,4898.64 h60
  text "X" at 12161,4895 h60
  text "62 MIL (1.6mm) +/-10%" at 12070.56,4735.92 h60
  text "THICKNESS:" at 11404.23,4731.64 h60
  text "X" at 11942.4,4731.64 h60
  text "OTHER" at 13355.46,4731.64 h60
  text "TOLERANCE:" at 11404.23,4573.64 h60
  text "X" at 12243.53,4573.64 h60
  text "ANSI IPC-6012 TYPE 3 CLASS 2" at 12430.48,4573.64 h60
  text "OTHER +/-" at 12430.46,4417.64 h60
  text "BOW & TWIST:" at 11404.23,4260.64 h60
  text "X" at 12243.53,4260.64 h60
  text "ANSI IPC-6012 TYPE 3 CLASS 2" at 12430.48,4260.64 h60
  text "OTHER +/-" at 12430.46,4102.13 h60
  text "DRILLING:" at 11329.46,3963.64 h60
  text "REFERENCE:" at 11404.23,3846.64 h60
  text "X" at 12052.46,3846.64 h60
  text "AS SHOWN" at 12239.46,3846.64 h60
  text "X" at 12953.46,3846.64 h60
  text "NC_DRILL FILES" at 13090.46,3846.64 h60
  text "PTH COPPER THICKNESS:" at 11404.23,3688.64 h60
  text "X" at 12534.46,3688.64 h60
  text "20-30 um" at 12671.46,3688.64 h60
  text "OTHER" at 13388.46,3688.64 h60
  text "BOARD FINISH:" at 11329.46,3529.64 h60
  text "SILKSCREEN:" at 11484.68,3411.64 h60
  text "X" at 12433.46,3411.64 h60
  text "TOP" at 12559.46,3411.64 h60
  text "X" at 12943.46,3411.64 h60
  text "BOTTOM" at 13070.46,3411.64 h60
  text "SILKSCREEN COLOR:" at 11484.68,3244.64 h60
  text "X" at 12432.42,3244.64 h60
  text "WHITE" at 12559.46,3244.64 h60
  text "OTHER" at 13070.46,3244.64 h60
  text "RED" at 13677.46,3094.44 h60
  text "GREEN" at 12690.46,3085.44 h60
  text "OTHER" at 13308.46,3085.44 h60
  text "X" at 13158,3084 h60
  text "SOLDER RESIST COLOR:" at 11484.68,3074.64 h60
  text "MATTE" at 12690.46,2915.44 h60
  text "SEMI-GLOSS" at 13308,2914.8 h60
  text "X" at 13157,2914 h60
  text "IMMERSION GOLD (ENIG)" at 12390.46,2726.92 h60
  text "ENEPIG" at 13728,2723.64 h60
  text "SURFACE FINISH:" at 11329.46,2722.64 h60
  text "X" at 12203.51,2722.64 h60
  text "IMM. TIN/SILVER OR EQUIV" at 11659,2565.64 h60
  text "OTHER" at 13090.46,2565.64 h60
  text "ARRAY/PANEL:" at 11329.46,2386.64 h60
  text "CUT AND TRIM PER M1 BOARD OUTLINE" at 12390.46,2382.35 h60
  text "N.C. ROUTE" at 12390.46,2230.64 h60
  text "X" at 13069.46,2230.64 h60
  text "V. SCORE" at 13256.46,2230.64 h60
  text "CERTIFICATION:" at 11329.46,2093.64 h60
  text "MATERIALS AND WORKMANSHIP FOR ALL PCBS" at 12054.46,2093.64 h60
  text "TO MEET OR EXCEED THE REQUIREMENTS OF:" at 12054.46,1995.64 h60
  text "X" at 11680.96,1859.13 h60
  text "ANSI IPC-A-600F CLASS ->" at 11819.96,1859.13 h60
  text "X" at 13459.02,1859.13 h60
  text "2" at 13577.96,1859.14 h60
  text "1" at 13262.96,1857.64 h60
  text "3" at 13931.96,1857.64 h60
  text "X" at 12495.02,1699.64 h60
  text "RoHS" at 12631.96,1699.64 h60
  text "OTHER" at 13276.36,1699.64 h60
  text "PER ORDER" at 13673.42,1699.64 h60
  text "ALL BOARDS MUST MEET OR EXCEED UL94-V0 REQUIREMENTS." at 11357,1534 h60
  text "PCB MUST BEAR THE UL94V-0 UL REGISTERED MATERIAL ID NUMBER" at 11357,1414 h60
  text "ADDITIONAL REQUIREMENTS:" at 11329.46,1240.64 h60
  text "MICROSECTION:" at 11404.23,1125.64 h60
  text "YES" at 12309.96,1125.64 h60
  text "REQUIRED" at 13171.46,969.49 h60
  text "BARE BOARD ELEC. TEST:" at 11404.23,966.64 h60
  text "NONE" at 12709.96,966.64 h60
  text "X" at 13044.46,966.64 h60
  text "PER ORDER" at 13763.46,966.64 h60
  text ".Layer_Name" at 577,-858.49 h60
M11 Gerber Information:
  lines w10: -292,-930.17 6308,-930.17 ; -292,-726.83 6310,-726.83 ; -292,-523.5 -292,-1133.5 3713,-1133.5 6310,-1133.5 6310,-523.5 -291.5,-523.5 -291.5,-1133.5 1284,-1133.5 ; 2173,-1133.5 2173,-523.5 ; 3440,-726.83 3440,-523.5 ; 4280,-726.83 4280,-523.5 ; 4902,-1140 4902,-937.17
  text "ALL ARTWORK VIEWED FROM TOP SIDE" at -228.5,-655.67 h60
  text "BOARD #:" at 2248,-655.67 h60
  text ".PRJ_Number" at 2793.5,-655.67 h60
  text "REV:" at 3638,-655.67 h60
  text ".PCB_Rev" at 3929.5,-655.67 h60
  text "SVN REV:" at 4476,-655.67 h60
  text ".VersionControl_RevNumber" at 4982,-655.67 h60
  text "LAYER NAME =" at -228.5,-858.49 h60
  text "TID #:" at 2248,-859 h60
  text ".TID" at 2793.5,-859 h60
  text "PLOT NAME =" at -228.5,-1064.34 h60
  text ".plot_File_Name" at 577,-1064.34 h60
  text "GENERATED    :" at 2250,-1064.34 h60
  text ".Print_Date" at 3119.5,-1064.34 h60
  text ".Print_Time" at 3848.5,-1064.34 h60
  text "TEXAS INSTRUMENTS" at 5113,-1064.34 h60
M12 Stackup:
  drawing of 295 lines, arcs and shapes, not listed
  text "Layer" at 9811.88,7812 h60
  text "Name" at 10221.79,7812 h60
  text "Material" at 11151.54,7812 h60
  text "Thickness" at 12011.3,7812 h60
  text "Constant" at 12661.14,7812 h60
  text "Board Layer Stack" at 13231,7812 h60
  text "1" at 9811.88,7692 h60
  text "Top Overlay" at 10221.79,7692 h60
  text "2" at 9811.88,7572 h60
  text "Top Solder" at 10221.79,7572 h60
  text "Solder Resist" at 11151.54,7572 h60
  text "0.40mil" at 12011.3,7572 h60
  text "3.5" at 12661.14,7572 h60
  text "3" at 9811.88,7452 h60
  text "Top Layer" at 10221.79,7452 h60
  text "Copper" at 11151.54,7452 h60
  text "1.40mil" at 12011.3,7452 h60
  text "4" at 9811.88,7332 h60
  text "Dielectric 1" at 10221.79,7332 h60
  text "FR-4" at 11151.54,7332 h60
  text "6.00mil" at 12011.3,7332 h60
  text "4.2" at 12661.14,7332 h60
  text "5" at 9811.88,7212 h60
  text "Layer 2 GND" at 10221.79,7212 h60
  text "Copper" at 11151.54,7212 h60
  text "1.42mil" at 12011.3,7212 h60
  text "6" at 9811.88,7092 h60
  text "Dielectric 2" at 10221.79,7092 h60
  text "FR-4" at 11151.54,7092 h60
  text "44.00mil" at 12011.3,7092 h60
  text "4.2" at 12661.14,7092 h60
  text "7" at 9811.88,6972 h60
  text "Layer 3 PWR" at 10221.79,6972 h60
  text "Copper" at 11151.54,6972 h60
  text "1.42mil" at 12011.3,6972 h60
  text "8" at 9811.88,6852 h60
  text "Dielectric1" at 10221.79,6852 h60
  text "FR-4" at 11151.54,6852 h60
  text "6.00mil" at 12011.3,6852 h60
  text "4.2" at 12661.14,6852 h60
  text "9" at 9811.88,6732 h60
  text "Bottom Layer" at 10221.79,6732 h60
  text "Copper" at 11151.54,6732 h60
  text "1.40mil" at 12011.3,6732 h60
  text "10" at 9811.88,6612 h60
  text "Bottom Solder" at 10221.79,6612 h60
  text "Solder Resist" at 11151.54,6612 h60
  text "0.40mil" at 12011.3,6612 h60
  text "3.5" at 12661.14,6612 h60
  text "11" at 9811.88,6492 h60
  text "Bottom Overlay" at 10221.79,6492 h60
  text ".Layer_Name" at 577,-858.49 h60
M13 Component Bodies Top:
  text ".Layer_Name" at 577,-858.49 h60
M14 Component Bodies Bottom:
  text ".Layer_Name" at 577,-858.49 h60
M15 Courtyards Top:
  text ".Layer_Name" at 577,-858.49 h60
M16 Courtyards Bottom:
  text ".Layer_Name" at 577,-858.49 h60
Drill Drawing:
  circle w10: c5363.72,2943.82 r27.63
  circle w10: c5363.72,2322.22 r16.58
  circle w10: c5363.72,2322.22 r27.63
  lines w10: 5336.09,2474.16 5391.34,2474.16 5363.72,2418.91 5336.09,2474.16 ; 5336.09,2598.48 5391.34,2598.48 5363.72,2543.23 5336.09,2598.48 ; 5336.09,2667.55 5363.72,2681.36 5391.34,2667.55 5377.53,2695.18 5391.34,2722.8 5363.72,2708.99 5336.09,2722.8 5349.9,2695.18 5336.09,2667.55 ; 5336.09,2791.87 5336.09,2805.68 5349.9,2819.5 5336.09,2833.31 5336.09,2847.12 5349.9,2847.12 5363.72,2833.31 5377.53,2847.12 5391.34,2847.12 5391.34,2833.31 5377.53,2819.5 5391.34,2805.68 5391.34,2791.87 5377.53,2791.87 5363.72,2805.68 5349.9,2791.87 5336.09,2791.87 ; 5336.09,3040.51 5391.34,3040.51 5391.34,3095.76 5336.09,3095.76 5336.09,3040.51 ; 5336.09,3178.64 5349.9,3178.64 5349.9,3164.83 5377.53,3164.83 5377.53,3178.64 5391.34,3178.64 5391.34,3206.27 5377.53,3206.27 5377.53,3220.08 5349.9,3220.08 5349.9,3206.27 5336.09,3206.27 5336.09,3178.64 ; 5336.09,3302.96 5349.9,3302.96 5363.72,3289.15 5377.53,3302.96 5391.34,3302.96 5377.53,3316.78 5391.34,3330.59 5377.53,3330.59 5363.72,3344.4 5349.9,3330.59 5336.09,3330.59 5349.9,3316.78 5336.09,3302.96 ; 5336.09,3441.1 5363.72,3413.47 5391.34,3441.1 5363.72,3468.72 5336.09,3441.1 ; 5347.14,2587.43 5380.29,2587.43 5363.72,2554.28 5347.14,2587.43
  lines w12: 5286,2257.29 8517.49,2257.29 ; 5286,3500.49 8517.49,3500.49 ; 5623.86,2132.97 5623.86,3624.81 ; 5955.86,2132.97 5955.86,3624.81 ; 6592.43,2132.97 6592.43,3624.81 ; 6851.57,2132.97 6851.57,3624.81 ; 7226.72,2132.97 7226.72,3624.81 ; 7951.05,2132.97 7951.05,3624.81 ; 5286,2132.97 8517.49,2132.97 8517.49,3624.81 5286,3624.81 5286,2132.97
  text "Symbol" at 5360.59,3537.79 h72
  text "Quantity" at 5661.16,3537.79 h72
  text "Finished Hole Size" at 5993.16,3537.79 h72
  text "Plated" at 6629.72,3537.79 h72
  text "Hole Type" at 6888.86,3537.79 h72
  text "Drill Layer Pair" at 7264.02,3537.79 h72
  text "Hole Tolerance" at 7988.35,3537.79 h72
  text "19" at 5661.16,3413.47 h60
  text "7.87mil (0.200mm)" at 5993.16,3413.47 h60
  text "PTH" at 6629.72,3413.47 h60
  text "Round" at 6888.86,3413.47 h60
  text "Top Layer - Bottom Layer" at 7264.02,3413.47 h60
  text "114" at 5661.16,3289.15 h60
  text "10.00mil (0.254mm)" at 5993.16,3289.15 h60
  text "PTH" at 6629.72,3289.15 h60
  text "Round" at 6888.86,3289.15 h60
  text "Top Layer - Bottom Layer" at 7264.02,3289.15 h60
  text "27" at 5661.16,3164.83 h60
  text "40.00mil (1.016mm)" at 5993.16,3164.83 h60
  text "PTH" at 6629.72,3164.83 h60
  text "Round" at 6888.86,3164.83 h60
  text "Top Layer - Bottom Layer" at 7264.02,3164.83 h60
  text "40" at 5661.16,3040.51 h60
  text "40.16mil (1.020mm)" at 5993.16,3040.51 h60
  text "PTH" at 6629.72,3040.51 h60
  text "Round" at 6888.86,3040.51 h60
  text "Top Layer - Bottom Layer" at 7264.02,3040.51 h60
  text "9" at 5661.16,2916.19 h60
  text "40.95mil (1.040mm)" at 5993.16,2916.19 h60
  text "PTH" at 6629.72,2916.19 h60
  text "Round" at 6888.86,2916.19 h60
  text "Top Layer - Bottom Layer" at 7264.02,2916.19 h60
  text "2" at 5661.16,2791.87 h60
  text "51.18mil (1.300mm)" at 5993.16,2791.87 h60
  text "PTH" at 6629.72,2791.87 h60
  text "Round" at 6888.86,2791.87 h60
  text "Top Layer - Bottom Layer" at 7264.02,2791.87 h60
  text "2" at 5661.16,2667.55 h60
  text "63.00mil (1.600mm)" at 5993.16,2667.55 h60
  text "PTH" at 6629.72,2667.55 h60
  text "Round" at 6888.86,2667.55 h60
  text "Top Layer - Bottom Layer" at 7264.02,2667.55 h60
  text "2" at 5661.16,2543.23 h60
  text "124.80mil (3.170mm)" at 5993.16,2543.23 h60
  text "PTH" at 6629.72,2543.23 h60
  text "Round" at 6888.86,2543.23 h60
  text "Top Layer - Bottom Layer" at 7264.02,2543.23 h60
  text "1" at 5661.16,2418.91 h60
  text "39.37mil (1.000mm)" at 5993.16,2418.91 h60
  text "PTH" at 6629.72,2418.91 h60
  text "Slot" at 6888.86,2418.91 h60
  text "Top Layer - Bottom Layer" at 7264.02,2418.91 h60
  text "1" at 5661.16,2294.59 h60
  text "39.37mil (1.000mm)" at 5993.16,2294.59 h60
  text "PTH" at 6629.72,2294.59 h60
  text "Slot" at 6888.86,2294.59 h60
  text "Top Layer - Bottom Layer" at 7264.02,2294.59 h60
  text "217 Total" at 5661.16,2170.27 h60
  text "Slot definitions :" at 5360.59,2083.25 h60
  text "Routed Path Length" at 5811.31,2083.25 h60
  text "= Calculated from tool start centre position to tool end centre position." at 6351.05,2083.25 h60
  text "Hole Length" at 5811.31,2033.52 h60
  text "= Routed Path Length + Tool Size = Slot length as defined in the PCB layout" at 6151.24,2033.52 h60
  text ".Layer_Name" at 577,-858.49 h60
M17 Embedded Cavity:
  text ".Layer_Name" at 577,-858.49 h60
M18 Embedded Assembly:
  text ".Layer_Name" at 577,-858.49 h60
M19 Embedded Keepout:
  text ".Layer_Name" at 577,-858.49 h60

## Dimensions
2250,50 to 2590,35 on M2 Board Dimensions
0,0 to 2300,0 on M2 Board Dimensions
0,-400 to 1000,-400 on M2 Board Dimensions
0,0 to 50,3400 on M2 Board Dimensions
